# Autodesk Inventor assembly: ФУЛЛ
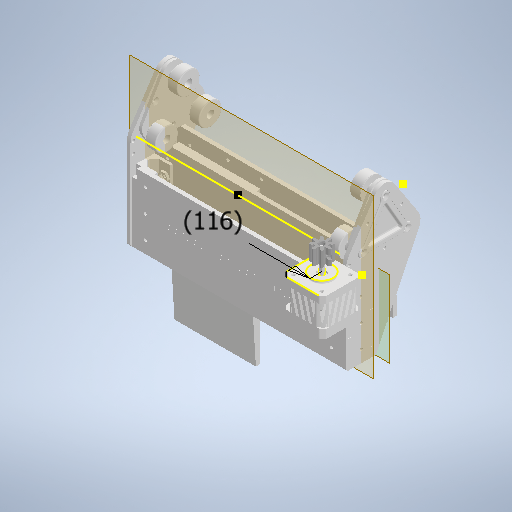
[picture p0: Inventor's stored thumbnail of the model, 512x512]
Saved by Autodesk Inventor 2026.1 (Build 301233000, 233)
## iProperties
Created: 2025-12
Part Number: ФУЛЛ
Document SubType Name: Assembly
Designer: Yury Melnikov
Author: Yury Melnikov
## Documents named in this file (8)
- C:\Users\user\Documents\Проекты\ВсОШ_РОБО\ФУЛЛ.iam
- C:\Users\user\Documents\Проекты\ВсОШ_РОБО\Стенд\СТЕНД.iam
- C:\Users\user\Documents\Проекты\ВсОШ_РОБО\Робот\Направляющие.ipt
- C:\Users\user\Documents\Проекты\ВсОШ_РОБО\Робот\Основная плита.ipt
- C:\Users\user\Documents\Проекты\ВсОШ_РОБО\Робот\Ребро жесткости.ipt
- C:\Users\user\Documents\Проекты\ВсОШ_РОБО\Робот\Направляющие_MIR1.ipt
- C:\Users\user\Documents\Проекты\ВсОШ_РОБО\Робот\Nema17H44.ipt
- C:\Users\user\Documents\Проекты\ВсОШ_РОБО\Робот\Шестеренки\Шестеренка.ipt
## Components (8 placed, 7 different names)
1. СТЕНД:1 [sub-assembly]
2. Основная плита:1 — Совмещение:3, Совмещение:4, Совмещение:5, Совмещение:6, Совмещение:9, Совмещение:10, Совмещение:11
3. Ребро жесткости:1 — Совмещение:9, Совмещение:10, Совмещение:11
4. Направляющие:1 — Совмещение:1, Касательность:1, Касательность:2, Совмещение:5, Совмещение:6, Совмещение:14, Совмещение:15
5. Направляющие_MIR1:1
6. Основная плита:2 — Совмещение:7, Совмещение:8, Совмещение:12
7. Nema17H44:1 — Совмещение:13, Совмещение:14, Совмещение:15, Совмещение:16
8. Шестеренка:1 — Совмещение:16
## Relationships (17: Mate 15, Tangent 2)
- Совмещение:1 [Mate]: Направляющие:1
- Касательность:1 [Tangent]: Направляющие:1
- Касательность:2 [Tangent]: Направляющие:1
- Совмещение:3 [Mate]: Основная плита:1
- Совмещение:4 [Mate]: Основная плита:1
- Совмещение:5 [Mate]: Основная плита:1 ↔ Направляющие:1
- Совмещение:6 [Mate]: Основная плита:1 ↔ Направляющие:1
- Совмещение:7 [Mate]: Основная плита:2
- Совмещение:8 [Mate]: Основная плита:2
- Совмещение:9 [Mate]: Основная плита:1 ↔ Ребро жесткости:1
- Совмещение:10 [Mate]: Основная плита:1 ↔ Ребро жесткости:1
- Совмещение:11 [Mate]: Основная плита:1 ↔ Ребро жесткости:1
- Совмещение:12 [Mate]: Основная плита:2
- Совмещение:13 [Mate]: Nema17H44:1
- Совмещение:14 [Mate]: Направляющие:1 ↔ Nema17H44:1
- Совмещение:15 [Mate]: Направляющие:1 ↔ Nema17H44:1
- Совмещение:16 [Mate]: Nema17H44:1 ↔ Шестеренка:1
